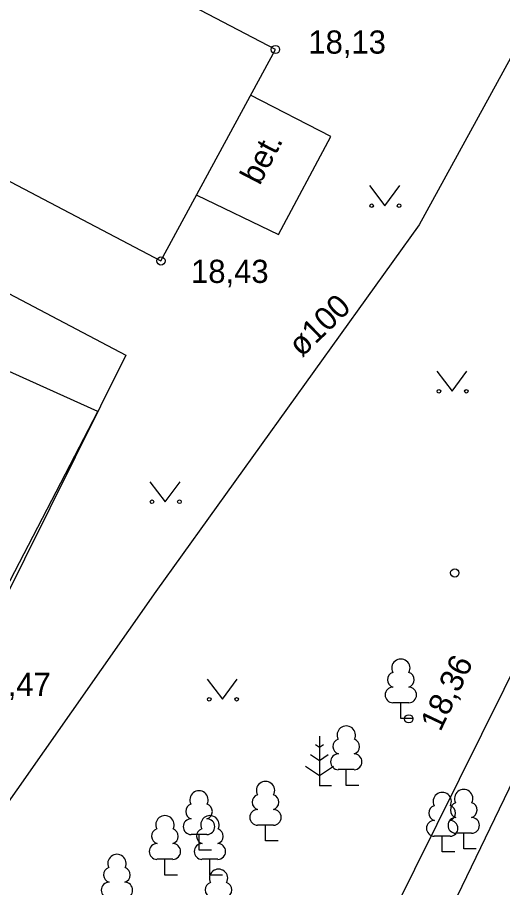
# Model space of a CAD drawing. Extents: x 713540 to 713867, y 6589774 to 6590061.
# Drawn here: x 713807.97 to 713822.63, y 6589948.37 to 6589974.67 of the extents above; entities that cross this region are included whole.
import ezdxf

# ---------------------------------------------------------------- set-up
doc = ezdxf.new("R2010")
doc.units = 0
for name, color, linetype in [('AED', 7, 'Continuous'), ('HALJASTUS', 7, 'Continuous'), ('HOONE', 7, 'Continuous'), ('HOONEDET', 7, 'Continuous'), ('KORGUS', 7, 'Continuous'), ('MPKAABEL', 7, 'Continuous'), ('PUU', 7, 'Continuous'), ('TEE', 7, 'Continuous'), ('TORU NR', 7, 'Continuous'), ('Слой 1', 7, 'Continuous')]:
    doc.layers.add(name, color=color, linetype=linetype)

msp = doc.modelspace()

# ---------------------------------------------------------------- linework, layer by layer
at = {"layer": 'AED'}
msp.add_lwpolyline([(713767.762, 6589909.249), (713772.443, 6589906.664), (713772.921, 6589907.533), (713780.72, 6589921.96), (713784.33, 6589929.01), (713786.08, 6589932.05), (713790.79, 6589929.6), (713799.05, 6589941.64), (713799.92, 6589942.78), (713800.93, 6589944.67), (713803.18, 6589949.29), (713806.07, 6589954.43), (713810.4, 6589962.76), (713799.4, 6589967.72), (713795.11, 6589969.78), (713786.56, 6589953.97)], dxfattribs=at)
at = {"layer": 'HALJASTUS'}
for p, q in [((713818.617, 6589969.587), (713819.08, 6589968.98)), ((713819.08, 6589968.98), (713819.526, 6589969.587)), ((713820.647, 6589963.977), (713821.11, 6589963.37)), ((713821.11, 6589963.37), (713821.556, 6589963.977)), ((713811.977, 6589960.637), (713812.44, 6589960.03)), ((713812.44, 6589960.03), (713812.886, 6589960.637)), ((713813.707, 6589954.667), (713814.17, 6589954.06)), ((713814.17, 6589954.06), (713814.616, 6589954.667))]:
    msp.add_line(p, q, dxfattribs=at)
for centre in [(713818.679, 6589968.98), (713819.508, 6589968.98), (713820.709, 6589963.37), (713821.538, 6589963.37), (713812.039, 6589960.03), (713812.868, 6589960.03), (713813.769, 6589954.06), (713814.598, 6589954.06)]:
    msp.add_circle(centre, 0.055, dxfattribs=at)
at = {"layer": 'HOONE'}
for points in [[(713853.13, 6590055.49), (713847.71, 6590042.61), (713840.88, 6590026.99), (713847.68, 6590019.43), (713836.38, 6589998.1), (713820.11, 6589968.4), (713812.16, 6589957.32), (713804.57, 6589946.51), (713791.35, 6589928.27), (713785.88, 6589931.15), (713778.18, 6589915.27), (713769.3, 6589896.72), (713774.33, 6589893.89), (713767.85, 6589880.54), (713761.86, 6589868.49), (713755.914, 6589856.728), (713753.12, 6589851.2), (713744.71, 6589834.75), (713742.63, 6589834)], [(713812.31, 6589967.31), (713815.77, 6589973.7), (713802.65, 6589980.56), (713799.28, 6589974.15), (713812.31, 6589967.31)]]:
    msp.add_lwpolyline(points, dxfattribs=at)
at = {"layer": 'HOONEDET'}
msp.add_lwpolyline([(713813.39, 6589969.3), (713815.86, 6589968.11), (713817.44, 6589971.07), (713815.02, 6589972.32)], dxfattribs=at)
at = {"layer": 'KORGUS'}
for centre in [(713815.77, 6589973.7), (713812.31, 6589967.31), (713821.19, 6589957.88), (713819.8, 6589953.47)]:
    msp.add_circle(centre, 0.125, dxfattribs=at)
at = {"layer": 'MPKAABEL'}
msp.add_lwpolyline([(713808.21, 6589921.82), (713821.27, 6589948.12), (713829.48, 6589965.13)], dxfattribs=at)
at = {"layer": 'PUU'}
for p, q in [((713819.8, 6589953.955), (713819.32, 6589953.955)), ((713819.56, 6589953.48), (713819.56, 6589953.955)), ((713819.94, 6589953.48), (713819.56, 6589953.48)), ((713817.1, 6589952.95), (713817.1, 6589951.45)), ((713817.1, 6589952.6), (713816.976, 6589952.683)), ((713817.224, 6589952.683), (713817.1, 6589952.6)), ((713817.1, 6589952.2), (713816.833, 6589952.378)), ((713817.367, 6589952.378), (713817.1, 6589952.2)), ((713816.676, 6589952.039), (713817.1, 6589951.757)), ((713817.1, 6589951.757), (713817.524, 6589952.039)), ((713818.15, 6589951.935), (713817.67, 6589951.935)), ((713817.91, 6589951.46), (713817.91, 6589951.935)), ((713817.46, 6589951.45), (713817.1, 6589951.45)), ((713818.29, 6589951.46), (713817.91, 6589951.46)), ((713815.71, 6589950.255), (713815.23, 6589950.255)), ((713815.47, 6589949.78), (713815.47, 6589950.255)), ((713813.7, 6589949.975), (713813.22, 6589949.975)), ((713813.46, 6589949.5), (713813.46, 6589949.975)), ((713821.05, 6589949.925), (713820.57, 6589949.925)), ((713820.81, 6589949.45), (713820.81, 6589949.925)), ((713821.7, 6589950.015), (713821.22, 6589950.015)), ((713821.46, 6589949.54), (713821.46, 6589950.015)), ((713815.85, 6589949.78), (713815.47, 6589949.78)), ((713813.84, 6589949.5), (713813.46, 6589949.5)), ((713821.19, 6589949.45), (713820.81, 6589949.45)), ((713821.84, 6589949.54), (713821.46, 6589949.54)), ((713812.67, 6589949.225), (713812.19, 6589949.225)), ((713812.43, 6589948.75), (713812.43, 6589949.225)), ((713814.03, 6589949.225), (713813.55, 6589949.225)), ((713813.79, 6589948.75), (713813.79, 6589949.225)), ((713812.81, 6589948.75), (713812.43, 6589948.75)), ((713814.17, 6589948.75), (713813.79, 6589948.75))]:
    msp.add_line(p, q, dxfattribs=at)
for centre, radius, start, end in [((713819.56, 6589955), 0.277, 332.5799, 207.4201), ((713819.39, 6589954.653), 0.233, 109.0217, 253.1415), ((713819.73, 6589954.653), 0.233, 286.8508, 70.9859), ((713819.323, 6589954.192), 0.238, 90.0016, 269.3953), ((713819.797, 6589954.192), 0.238, 270.6047, 89.9984), ((713817.91, 6589952.98), 0.277, 332.5799, 207.4201), ((713817.74, 6589952.633), 0.233, 109.0217, 253.1415), ((713818.08, 6589952.633), 0.233, 286.8508, 70.9859), ((713817.673, 6589952.172), 0.238, 90.0016, 269.3953), ((713818.147, 6589952.172), 0.238, 270.6047, 89.9984), ((713815.47, 6589951.3), 0.277, 332.5799, 207.4201), ((713813.46, 6589951.02), 0.277, 332.5799, 207.4201), ((713820.81, 6589950.97), 0.277, 332.5799, 207.4201), ((713821.46, 6589951.06), 0.277, 332.5799, 207.4201), ((713815.3, 6589950.953), 0.233, 109.0217, 253.1415), ((713815.64, 6589950.953), 0.233, 286.8508, 70.9859), ((713813.29, 6589950.673), 0.233, 109.0217, 253.1415), ((713813.63, 6589950.673), 0.233, 286.8508, 70.9859), ((713815.233, 6589950.492), 0.238, 90.0016, 269.3953), ((713815.707, 6589950.492), 0.238, 270.6047, 89.9984), ((713820.64, 6589950.623), 0.233, 109.0217, 253.1415), ((713820.98, 6589950.623), 0.233, 286.8508, 70.9859), ((713821.29, 6589950.713), 0.233, 109.0217, 253.1415), ((713821.63, 6589950.713), 0.233, 286.8508, 70.9859), ((713812.43, 6589950.27), 0.277, 332.5799, 207.4201), ((713813.223, 6589950.212), 0.238, 90.0016, 269.3953), ((713813.79, 6589950.27), 0.277, 332.5799, 207.4201), ((713813.697, 6589950.212), 0.238, 270.6047, 89.9984), ((713821.223, 6589950.252), 0.238, 90.0016, 269.3953), ((713821.697, 6589950.252), 0.238, 270.6047, 89.9984), ((713820.573, 6589950.162), 0.238, 90.0016, 269.3953), ((713821.047, 6589950.162), 0.238, 270.6047, 89.9984), ((713812.26, 6589949.923), 0.233, 109.0217, 253.1415), ((713812.6, 6589949.923), 0.233, 286.8508, 70.9859), ((713813.62, 6589949.923), 0.233, 109.0217, 253.1415), ((713813.96, 6589949.923), 0.233, 286.8508, 70.9859), ((713812.193, 6589949.462), 0.238, 90.0016, 269.3953), ((713812.667, 6589949.462), 0.238, 270.6047, 89.9984), ((713813.553, 6589949.462), 0.238, 90.0016, 269.3953), ((713814.027, 6589949.462), 0.238, 270.6047, 89.9984), ((713810.98, 6589949.1), 0.277, 332.5799, 207.4201), ((713810.81, 6589948.753), 0.233, 109.0217, 253.1415), ((713811.15, 6589948.753), 0.233, 286.8508, 70.9859), ((713814.05, 6589948.65), 0.277, 332.5799, 207.4201), ((713810.743, 6589948.292), 0.238, 90.0016, 269.3953), ((713811.217, 6589948.292), 0.238, 270.6047, 89.9984), ((713813.88, 6589948.303), 0.233, 109.0217, 253.1415), ((713814.22, 6589948.303), 0.233, 286.8508, 70.9859)]:
    msp.add_arc(centre, radius, start, end, dxfattribs=at)
at = {"layer": 'TEE'}
msp.add_lwpolyline([(713815.93, 6589940.77), (713824.03, 6589957.09), (713827.45, 6589963.93), (713830.46, 6589970.28), (713832.64, 6589974.38), (713839.88, 6589989.01), (713841.08, 6589990.62), (713843.27, 6589993.16), (713845.38, 6589995.42), (713849.26, 6589999.36), (713853.21, 6590002.79), (713857.03, 6590005.94), (713860.48, 6590008.86), (713861.98, 6590009.43), (713864.03, 6590009.89), (713866.671, 6590010.167)], dxfattribs=at)
at = {"layer": 'Слой 1'}
msp.add_lwpolyline([(713800.41, 6589978.59), (713796.9, 6589972.02), (713811.25, 6589964.46), (713800.51, 6589942.86), (713790.89, 6589929.51), (713786.76, 6589932.33), (713753.32, 6589950.56), (713774.49, 6589992.04)], close=True, dxfattribs=at)

# ---------------------------------------------------------------- texts
at = {"layer": 'KORGUS'}
for s, p in [('18,13', (713816.766, 6589973.575)), ('18,43', (713813.221, 6589966.645)), ('18,47', (713806.638, 6589954.165))]:
    msp.add_text(s, height=0.7, dxfattribs=at).set_placement(p)
msp.add_text('18,36', height=0.7, rotation=64.6392, dxfattribs=at).set_placement((713820.754, 6589953.059))
at = {"layer": 'TEE'}
msp.add_text('bet.', height=0.7, rotation=62.4979, dxfattribs=at).set_placement((713815.294, 6589969.57))
at = {"layer": 'TORU NR'}
msp.add_text('ø100', height=0.7, rotation=44.2205, dxfattribs=at).set_placement((713816.566, 6589964.377))

doc.saveas('drawing.dxf')
